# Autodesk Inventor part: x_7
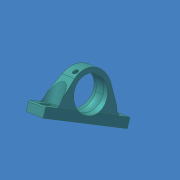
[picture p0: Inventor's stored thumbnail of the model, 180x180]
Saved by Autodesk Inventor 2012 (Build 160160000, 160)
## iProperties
Company: CAD-Verlag
Part Number: x_7
Document SubType Name: Modeling
Created: 2004-09
Material: Standard
Designer: Greiling
Manufacturer: Standard
Standards Organization: Custom
Density: 1 g/cm^3
Control State: 0
Master: False
Checked Out: False
Shininess: 64.0
Length Units: 11269
Angle Units: 11279
Time Units: 11290
Mass Units: 11283
Length Display Precision: 3
Angle Display Precision: 2
Compacted: True
Übersetzungsnorm: STEP AP214CD
Dateiname: w2c22665.stp
Vorprozessor: ACIS
Postprozessor: Build: 081d, Release: 8 SP1 - Date: Tue 01/26/2004
Gesendete Einheiten: MILLIMETERS
Unbestimmtheit: 1e-06
Density: 0.0
Volumn: 0.0
Area: 0.0
PropertySet Name: Model Information
Author: Jürgen Kronas
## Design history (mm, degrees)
feature "Basis1"
node "Volumenkörper1"
node "Volumenkörpern"
node "Oberflächenkörpern"
